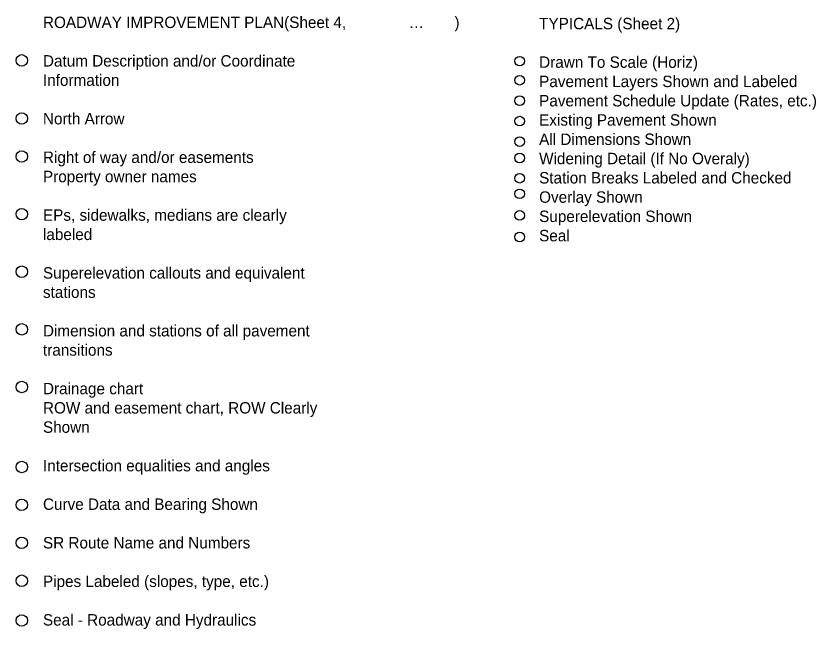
# Model space of a CAD drawing. Extents: x 573078 to 573156.2, y -55225.7 to -55195.8.
# Drawn here: x 573121.21 to 573156.2, y -55225.65 to -55198.82 of the extents above; entities that cross this region are included whole.
import ezdxf

# ---------------------------------------------------------------- set-up
doc = ezdxf.new("R2010")
doc.units = 0
doc.layers.add('Scratch_Level_0', color=7, linetype='Continuous')

msp = doc.modelspace()

# ---------------------------------------------------------------- linework, layer by layer
at = {"layer": 'Scratch_Level_0'}
for centre, radius in [((573121.46, -55200.762), 0.251), ((573143.241, -55200.794), 0.21), ((573143.241, -55201.629), 0.21), ((573143.241, -55202.525), 0.21), ((573121.46, -55203.303), 0.251), ((573143.241, -55203.42), 0.21), ((573143.241, -55204.316), 0.21), ((573121.46, -55204.966), 0.251), ((573143.241, -55205.033), 0.21), ((573143.241, -55205.919), 0.21), ((573143.241, -55206.604), 0.21), ((573121.46, -55207.489), 0.251), ((573143.241, -55207.547), 0.21), ((573143.241, -55208.49), 0.21), ((573121.46, -55210.012), 0.251), ((573121.46, -55212.536), 0.251), ((573121.46, -55215.059), 0.251), ((573121.46, -55218.56), 0.251), ((573121.46, -55220.22), 0.251), ((573121.46, -55221.879), 0.251), ((573121.46, -55223.538), 0.251), ((573121.46, -55225.281), 0.251)]:
    msp.add_circle(centre, radius, dxfattribs=at)

# ---------------------------------------------------------------- texts
for s, p in [('ROADWAY IMPROVEMENT PLAN(Sheet 4, ', (573122.388, -55199.345)), (')', (573140.388, -55199.345)), ('TYPICALS (Sheet 2)', (573144.092, -55199.4)), ('…', (573138.388, -55199.345)), ('Datum Description and/or Coordinate ', (573122.388, -55201.032)), ('Drawn To Scale (Horiz)', (573144.092, -55201.087)), ('Information', (573122.388, -55201.876)), ('Pavement Layers Shown and Labeled', (573144.092, -55201.931)), ('Pavement Schedule Update (Rates, etc.)', (573144.092, -55202.775)), ('North Arrow', (573122.388, -55203.563)), ('Existing Pavement Shown', (573144.092, -55203.619)), ('All Dimensions Shown', (573144.092, -55204.462)), ('Right of way and/or easements', (573122.388, -55205.251)), ('Widening Detail (If No Overaly)', (573144.092, -55205.306)), ('Property owner names', (573122.388, -55206.095)), ('Station Breaks Labeled and Checked', (573144.092, -55206.15)), ('Overlay Shown', (573144.092, -55206.994)), ('EPs, sidewalks, medians are clearly ', (573122.388, -55207.782)), ('Superelevation Shown', (573144.092, -55207.837)), ('labeled', (573122.388, -55208.626)), ('Seal', (573144.092, -55208.681)), ('Superelevation callouts and equivalent ', (573122.388, -55210.313)), ('stations', (573122.388, -55211.157)), ('Dimension and stations of all pavement ', (573122.388, -55212.845)), ('transitions', (573122.388, -55213.688)), ('Drainage chart', (573122.388, -55215.376)), ('ROW and easement chart, ROW Clearly', (573122.388, -55216.22)), ('Shown', (573122.388, -55217.063)), ('Intersection equalities and angles', (573122.388, -55218.751)), ('Curve Data and Bearing Shown', (573122.388, -55220.438)), ('SR Route Name and Numbers', (573122.388, -55222.126)), ('Pipes Labeled (slopes, type, etc.)', (573122.388, -55223.813)), ('Seal - Roadway and Hydraulics', (573122.388, -55225.501))]:
    msp.add_text(s, height=0.5, dxfattribs=at).set_placement(p)

doc.saveas('drawing.dxf')
